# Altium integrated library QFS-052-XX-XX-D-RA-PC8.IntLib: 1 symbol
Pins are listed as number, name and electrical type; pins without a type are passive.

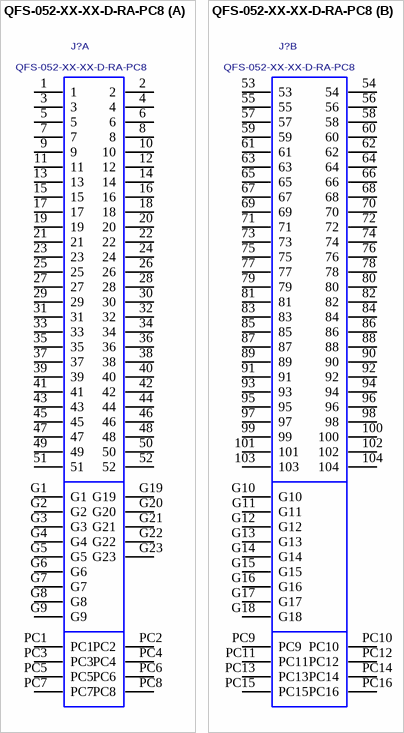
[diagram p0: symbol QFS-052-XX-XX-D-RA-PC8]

## QFS-052-XX-XX-D-RA-PC8
designator J?
0.635MM DUAL ROW RIGHT ANGLE SOCKET ASSEMBLY, 8 POWER PINS PER END.; MANUFACTURER: SAMTEC
footprint QFS-052-XX-XX-D-RA-PC8
part A pins: 1, 2, 3, 4, 5, 6, 7, 8, 9, 10, 11, 12, 13, 14, 15, 16, 17, 18, 19, 20, 21, 22, 23, 24, 25, 26, 27, 28, 29, 30, 31, 32, 33, 34, 35, 36, 37, 38, 39, 40, 41, 42, 43, 44, 45, 46, 47, 48, 49, 50, 51, 52, G1, G2, G3, G4, G5, G6, G7, G8, G9, G19, G20, G21, G22, G23, PC1, PC2, PC3, PC4, PC5, PC6, PC7, PC8
part B pins: 53, 54, 55, 56, 57, 58, 59, 60, 61, 62, 63, 64, 65, 66, 67, 68, 69, 70, 71, 72, 73, 74, 75, 76, 77, 78, 79, 80, 81, 82, 83, 84, 85, 86, 87, 88, 89, 90, 91, 92, 93, 94, 95, 96, 97, 98, 99, 100, 101, 102, 103, 104, G10, G11, G12, G13, G14, G15, G16, G17, G18, PC9, PC10, PC11, PC12, PC13, PC14, PC15, PC16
